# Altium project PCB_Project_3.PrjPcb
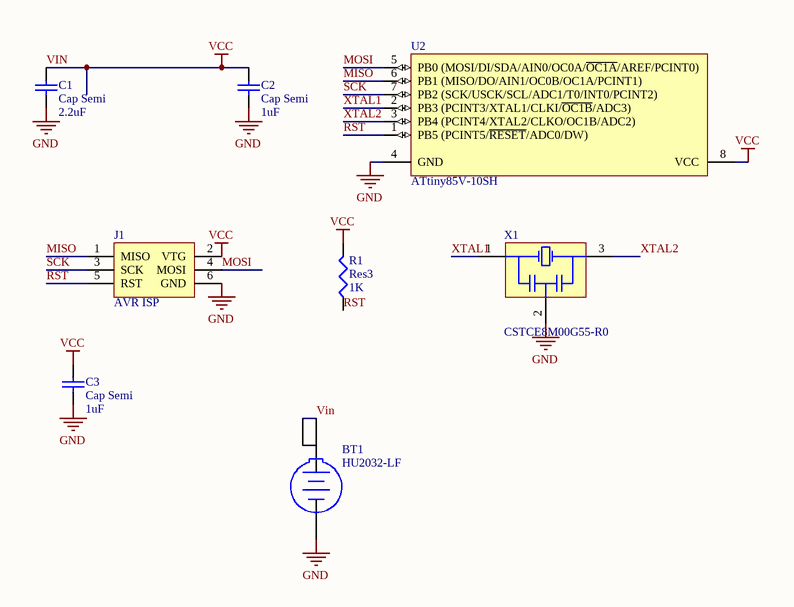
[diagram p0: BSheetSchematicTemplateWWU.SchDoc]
DraftsmanName: [GlobalDraftsmanName]; EngineerName: [GlobalEngineerName]; GlobalDate: [GlobalDate]; GlobalTitle: [GlobalTitle]; RevNumber: [GlobalRevNumber]
1 sheet, 8 parts. Net scope: flat (ports and power ports of the same name join across sheets).
Board file: 2LayerPCBTemplateWWU.PcbDoc

## Sheet BSheetSchematicTemplateWWU.SchDoc: [SheetTitle]
size B; Date: [Date]

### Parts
BT1  HU2032-LF  [RENA-HU2032-LF_V]
C1  Cap Semi  value 2.2uF  [1608[0603]]
C2  Cap Semi  value 1uF  [1608[0603]]
C3  Cap Semi  value 1uF  [1608[0603]]
J1  AVR ISP  [AVR_ISP]
R1  Res3  value 1K  [J1-0603]
U2  ATtiny85V-10SH  [8S2_N]
X1  CSTCE8M00G55-R0  [MURA-CSTCE_G_A-3_V]

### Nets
GND: BT1.3(-) C1.1 C2.1 C3.1 J1.6(GND) U2.4(GND) X1.2(GND)
VIN: BT1.1(+) BT1.2(+) C1.2 C2.2 C3.2 J1.2(VTG) R1.2 U2.8(VCC)  [also labelled VCC]
MISO: J1.1(MISO) U2.6(PB1_(MISO/DO/AIN1/OC0B/OC1A/PCINT1))
MOSI: J1.4(MOSI) U2.5(PB0_(MOSI/DI/SDA/AIN0/OC0A/~{OC1A}/AREF/PCINT0))
RST: J1.5(RST) R1.1 U2.1(PB5_(PCINT5/~{RESET}/ADC0/DW))
SCK: J1.3(SCK) U2.7(PB2_(SCK/USCK/SCL/ADC1/T0/INT0/PCINT2))
XTAL1: U2.2(PB3_(PCINT3/XTAL1/CLKI/~{OC1B}/ADC3)) X1.1(X1)
XTAL2: U2.3(PB4_(PCINT4/XTAL2/CLKO/OC1B/ADC2)) X1.3(X2)

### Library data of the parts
BT1 = CMP-2000-06429-1: Coin Cell Battery Holder, CR2032, Horizontal, -40 to 100 degC, 3-Pin THD, RoHS, Tray; Brand: Renata; Battery Cell Size: 20mm
C1-C3 = Cap Semi: Capacitor (Semiconductor SIM Model)
J1 = AVR_ISP: AVR ISP POGO CONNECTOR
R1 = Res3: Resistor
U2 = CMP-0093-00338-1: 8-bit AVR Microcontroller, 10MHz, 1.8-5.5V, 8K Flash, 512 Bytes EEPROM, 512 Bytes SRAM, Industrial Grade (-40°C to 85°C), 8-Lead SOIC, Pb-Free
X1 = CMP-2100-03620-1: Ceramic Resonator, 8 MHz, +/- 0.5%, -20 to 80 degC, 3-Pin SMD, RoHS, Tape and Reel; Manufacturer: Murata; Capacitance: 33pF; Frequency Stability: 0.2%; Self Resonant Frequency: 8MHz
